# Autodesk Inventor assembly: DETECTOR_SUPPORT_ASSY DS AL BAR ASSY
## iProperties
Shininess: 64.0
Length Units: 11272
Angle Units: 11279
Time Units: 11290
Mass Units: 11286
Length Display Precision: 3
Angle Display Precision: 2
Compacted: True
Part Number: DETECTOR_SUPPORT_ASSY DS AL BAR ASSY
Document SubType Name: Assembly
Created: 2004-08
Designer: John Blackburn
Manufacturer: Standard
Standards Organization: Custom
Density: 0.0
Volumn: 0.0
Area: 0.0
PropertySet Name: Model Information
Control State: 0
Master: False
Checked Out: False
Author: John Blackburn
